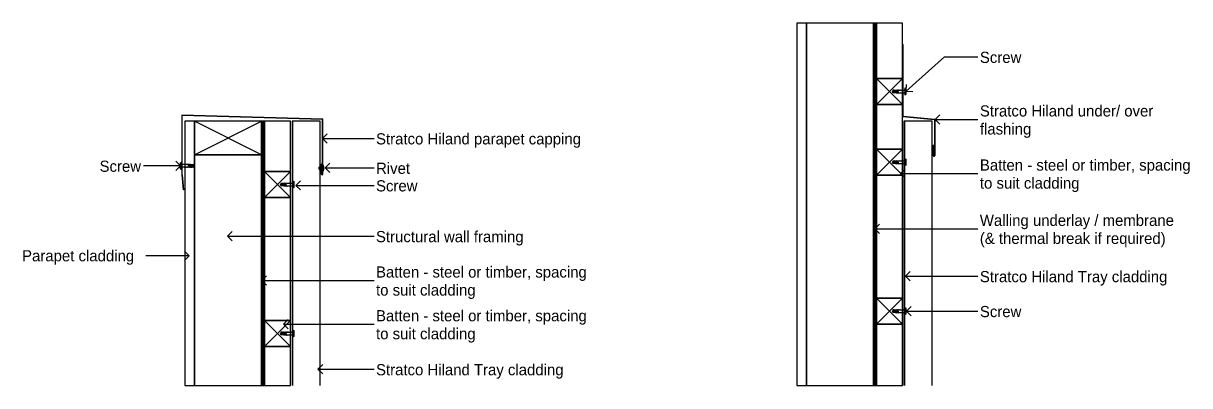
# Model space of a CAD drawing. Extents: x -2.36 to 6.66, y -3.72 to 4.13.
# Drawn here: x -2.359 to -0.792, y 3.645 to 4.131 of the extents above; entities that cross this region are included whole.
import ezdxf

# ---------------------------------------------------------------- set-up
doc = ezdxf.new("R2010")
doc.units = 0
for name, color, linetype in [('A-____-____-IDEN', 7, 'Continuous'), ('A-DETL-____-MEDM', 7, 'Continuous'), ('A-DETL-GENF-OTLN', 7, 'Continuous'), ('A-WALL-____-MCUT', 7, 'Continuous'), ('A-WALL-____-PATT', 7, 'Continuous'), ('A-WALL-FNSH-MCUT', 7, 'Continuous'), ('G-____-____-TEXT', 7, 'Continuous')]:
    doc.layers.add(name, color=color, linetype=linetype)

# ---------------------------------------------------------------- blocks, each defined once
blk = doc.blocks.new('Detail_Stratco_Cladding Side Profile - 38mm-Hiland Nailstrip Parapet')
at = {"layer": 'A-DETL-____-MEDM'}
for p, q in [((-1.9981, 4), (-1.9981, 3.645)), ((-1.9971, 4), (-1.9981, 4)), ((-1.9971, 3.645), (-1.9971, 4))]:
    blk.add_line(p, q, dxfattribs=at)
at = {"layer": 'A-DETL-GENF-OTLN'}
for p, q in [((-1.9601, 4), (-1.9981, 4)), ((-1.9601, 3.645), (-1.9601, 4))]:
    blk.add_line(p, q, dxfattribs=at)
blk = doc.blocks.new('Detail_Stratco_Hiland_Tray_Parapet - Rib Height 38mm-Hiland Nailstrip Parapet')
at = {"layer": 'A-DETL-GENF-OTLN'}
for p, q in [((-1.9566, 4.003), (-2.146, 4.008)), ((-2.146, 4.008), (-2.146, 3.928)), ((-2.1455, 3.928), (-2.1455, 4.0075)), ((-1.9571, 4.0025), (-2.1455, 4.0075)), ((-1.9571, 3.929), (-1.9571, 4.0025)), ((-1.9566, 3.929), (-1.9566, 4.003)), ((-1.9586, 3.929), (-1.9586, 3.943)), ((-1.9586, 3.943), (-1.9581, 3.943)), ((-1.9581, 3.929), (-1.9581, 3.943)), ((-2.146, 3.928), (-2.1445, 3.908)), ((-2.1455, 3.928), (-2.144, 3.908)), ((-2.144, 3.908), (-2.1445, 3.908))]:
    blk.add_line(p, q, dxfattribs=at)
for radius in [0.001, 0.0005]:
    blk.add_arc((-1.9576, 3.929), radius, 180, 0, dxfattribs=at)
blk = doc.blocks.new('DET_ST_Framing Detail Timber - 35x35 Batten-Hiland Nailstrip Parapet')
at = {"layer": 'A-DETL-____-MEDM'}
for p, q in [((-2, 3.9325), (-2.035, 3.9325)), ((-2.035, 3.9325), (-2.035, 3.8975)), ((-2, 3.8975), (-2, 3.9325)), ((-2.035, 3.8975), (-2, 3.8975))]:
    blk.add_line(p, q, dxfattribs=at)
at = {"layer": 'A-DETL-GENF-OTLN'}
for p, q in [((-2.035, 3.9325), (-2, 3.8975)), ((-2, 3.9325), (-2.035, 3.8975))]:
    blk.add_line(p, q, dxfattribs=at)
blk = doc.blocks.new('DET_ST_Framing Detail Timber - 45x90-Hiland Nailstrip Parapet')
at = {"layer": 'A-DETL-____-MEDM'}
for p, q in [((-2.039, 4), (-2.129, 4)), ((-2.129, 4), (-2.129, 3.955)), ((-2.039, 3.955), (-2.039, 4)), ((-2.129, 3.955), (-2.039, 3.955))]:
    blk.add_line(p, q, dxfattribs=at)
at = {"layer": 'A-DETL-GENF-OTLN'}
for p, q in [((-2.039, 3.955), (-2.129, 4)), ((-2.129, 3.955), (-2.039, 4))]:
    blk.add_line(p, q, dxfattribs=at)
blk = doc.blocks.new('DET_Screw Metal Wafer - DET_Screw Metal Wafer-Hiland Nailstrip Parapet')
at = {"layer": 'A-DETL-GENF-OTLN'}
for p, q in [((-1.9971, 3.9191), (-1.9971, 3.9109)), ((-1.9964, 3.9196), (-1.9955, 3.919)), ((-1.9964, 3.9104), (-1.9964, 3.9196)), ((-1.9955, 3.919), (-1.9955, 3.911)), ((-2.013, 3.9167), (-2.0136, 3.915)), ((-2.0136, 3.915), (-2.006, 3.915)), ((-2.0128, 3.9127), (-2.0136, 3.915)), ((-2.013, 3.9167), (-1.9979, 3.9167)), ((-2.0087, 3.9132), (-2.0128, 3.9127)), ((-2.0123, 3.9167), (-2.0121, 3.9175)), ((-2.0102, 3.9167), (-2.01, 3.9175)), ((-2.0087, 3.9132), (-1.9979, 3.9132)), ((-2.0084, 3.9125), (-2.0081, 3.9132)), ((-2.0081, 3.9167), (-2.0079, 3.9175)), ((-2.0063, 3.9125), (-2.006, 3.9132)), ((-2.006, 3.9167), (-2.0058, 3.9175)), ((-2.006, 3.915), (-2.0055, 3.9132)), ((-2.0042, 3.9125), (-2.0039, 3.9132)), ((-2.0039, 3.9167), (-2.0037, 3.9175)), ((-2.0021, 3.9125), (-2.0018, 3.9132)), ((-2.0018, 3.9167), (-2.0016, 3.9175)), ((-2, 3.9125), (-1.9997, 3.9132)), ((-1.9997, 3.9167), (-1.9995, 3.9175)), ((-1.9955, 3.911), (-1.9964, 3.9104))]:
    blk.add_line(p, q, dxfattribs=at)
for centre, radius, start, end in [((-1.9966, 3.9191), 0.0005, 66.3302, 180), ((-1.9979, 3.9175), 0.0008, 270, 0), ((-1.9979, 3.9124), 0.0008, 0, 90), ((-1.9966, 3.9109), 0.0005, 180, 293.6698)]:
    blk.add_arc(centre, radius, start, end, dxfattribs=at)
blk = doc.blocks.new('DET_Rivet - DET_Rivet-Hiland Nailstrip Parapet')
at = {"layer": 'A-DETL-GENF-OTLN'}
for p, q in [((-1.9621, 3.9377), (-1.9621, 3.9362)), ((-1.9601, 3.9377), (-1.9574, 3.9377)), ((-1.9601, 3.9362), (-1.9601, 3.9377)), ((-1.9601, 3.9362), (-1.9574, 3.9362)), ((-1.9566, 3.94), (-1.9566, 3.9385)), ((-1.9566, 3.9354), (-1.9566, 3.9385)), ((-1.9566, 3.9354), (-1.9566, 3.9338))]:
    blk.add_line(p, q, dxfattribs=at)
for centre, radius, start, end in [((-1.9611, 3.9377), 0.001, 0, 180), ((-1.9611, 3.9362), 0.001, 180, 0), ((-1.9574, 3.9385), 0.0008, 270, 0), ((-1.9574, 3.9354), 0.0008, 0, 90), ((-1.9561, 3.94), 0.0005, 52.978, 180), ((-1.9561, 3.9338), 0.0005, 180, 307.022), ((-1.9645, 3.9369), 0.00934, 337.9949, 22.0051)]:
    blk.add_arc(centre, radius, start, end, dxfattribs=at)
blk = doc.blocks.new('DET_ST_Framing Detail Timber - 35x35 Batten-Hiland Nailstrip Parapet 1')
at = {"layer": 'A-DETL-____-MEDM'}
for p, q in [((-2, 3.9625), (-2.035, 3.9625)), ((-2.035, 3.9625), (-2.035, 3.9275)), ((-2, 3.9275), (-2, 3.9625)), ((-2.035, 3.9275), (-2, 3.9275))]:
    blk.add_line(p, q, dxfattribs=at)
at = {"layer": 'A-DETL-GENF-OTLN'}
for p, q in [((-2.035, 3.9625), (-2, 3.9275)), ((-2, 3.9625), (-2.035, 3.9275))]:
    blk.add_line(p, q, dxfattribs=at)
blk = doc.blocks.new('Detail_Stratco_Cladding Side Profile - 38mm-Hiland Nailstrip Parapet 1')
at = {"layer": 'A-DETL-____-MEDM'}
for p, q in [((-1.9981, 4), (-1.9981, 3.645)), ((-1.9971, 4), (-1.9981, 4)), ((-1.9971, 3.645), (-1.9971, 4))]:
    blk.add_line(p, q, dxfattribs=at)
at = {"layer": 'A-DETL-GENF-OTLN'}
for p, q in [((-1.9601, 4), (-1.9981, 4)), ((-1.9601, 3.645), (-1.9601, 4))]:
    blk.add_line(p, q, dxfattribs=at)
blk = doc.blocks.new('Detail_Stratco_Hiland_Tray_Under Over Flashing - Rib Height 38mm-Hiland Nailstrip Parapet 1')
at = {"layer": 'A-DETL-GENF-OTLN'}
for p, q in [((-1.9997, 4.0063), (-1.9997, 4.103)), ((-1.9997, 4.103), (-1.9992, 4.103)), ((-1.9992, 4.0067), (-1.9992, 4.103)), ((-1.9997, 4.0063), (-1.9572, 4.0025)), ((-1.9992, 4.0067), (-1.9567, 4.003)), ((-1.9572, 4.0025), (-1.9572, 3.954)), ((-1.9567, 4.003), (-1.9567, 3.954)), ((-1.9587, 3.968), (-1.9587, 3.954)), ((-1.9587, 3.968), (-1.9582, 3.968)), ((-1.9582, 3.968), (-1.9582, 3.954))]:
    blk.add_line(p, q, dxfattribs=at)
for radius in [0.001, 0.0005]:
    blk.add_arc((-1.9577, 3.954), radius, 180, 0, dxfattribs=at)
blk = doc.blocks.new('DET_Screw Metal Wafer - DET_Screw Metal Wafer-Hiland Nailstrip Parapet 1')
at = {"layer": 'A-DETL-GENF-OTLN'}
for p, q in [((-1.9964, 3.9496), (-1.9955, 3.949)), ((-1.9964, 3.9404), (-1.9964, 3.9496)), ((-2.013, 3.9467), (-2.0136, 3.945)), ((-2.0136, 3.945), (-2.006, 3.945)), ((-2.0128, 3.9427), (-2.0136, 3.945)), ((-2.013, 3.9467), (-1.9979, 3.9467)), ((-2.0087, 3.9432), (-2.0128, 3.9427)), ((-2.0123, 3.9467), (-2.0121, 3.9475)), ((-2.0102, 3.9467), (-2.01, 3.9475)), ((-2.0087, 3.9432), (-1.9979, 3.9432)), ((-2.0084, 3.9425), (-2.0081, 3.9432)), ((-2.0081, 3.9467), (-2.0079, 3.9475)), ((-2.0063, 3.9425), (-2.006, 3.9432)), ((-2.006, 3.9467), (-2.0058, 3.9475)), ((-2.006, 3.945), (-2.0055, 3.9432)), ((-2.0042, 3.9425), (-2.0039, 3.9432)), ((-2.0039, 3.9467), (-2.0037, 3.9475)), ((-2.0021, 3.9425), (-2.0018, 3.9432)), ((-2.0018, 3.9467), (-2.0016, 3.9475)), ((-2, 3.9425), (-1.9997, 3.9432)), ((-1.9997, 3.9467), (-1.9995, 3.9475)), ((-1.9971, 3.9491), (-1.9971, 3.9409)), ((-1.9955, 3.941), (-1.9964, 3.9404)), ((-1.9955, 3.949), (-1.9955, 3.941))]:
    blk.add_line(p, q, dxfattribs=at)
for centre, radius, start, end in [((-1.9966, 3.9491), 0.0005, 66.3302, 180), ((-1.9979, 3.9475), 0.0008, 270, 0), ((-1.9979, 3.9425), 0.0008, 0, 90), ((-1.9966, 3.9409), 0.0005, 180, 293.6698)]:
    blk.add_arc(centre, radius, start, end, dxfattribs=at)

msp = doc.modelspace()

# ---------------------------------------------------------------- linework, layer by layer
at = {"layer": 'A-____-____-IDEN'}
for p, q in [((-1.1729, 4.0404), (-1.1212, 4.0864)), ((-1.1212, 4.0864), (-1.0765, 4.0864)), ((-1.1729, 4.0404), (-1.1724, 4.0492)), ((-1.1729, 4.0404), (-1.164, 4.0399)), ((-1.1341, 4.0024), (-1.1278, 4.0086)), ((-1.1341, 4.0024), (-1.1278, 3.9961)), ((-1.1341, 4.0024), (-1.1261, 4.0024)), ((-1.1261, 4.0024), (-1.0765, 4.0024)), ((-1.957, 3.977), (-1.9508, 3.9832)), ((-1.957, 3.977), (-1.9508, 3.9707)), ((-1.957, 3.977), (-1.9325, 3.977)), ((-1.9325, 3.977), (-1.8879, 3.977)), ((-2.1646, 3.9402), (-2.1978, 3.9402)), ((-2.1479, 3.9402), (-2.1646, 3.9402)), ((-2.1479, 3.9402), (-2.1542, 3.9465)), ((-2.1479, 3.9402), (-2.1542, 3.934)), ((-1.9535, 3.9375), (-1.9473, 3.9437)), ((-1.9535, 3.9375), (-1.9473, 3.9312)), ((-1.9535, 3.9375), (-1.943, 3.9375)), ((-1.943, 3.9375), (-1.8879, 3.9375)), ((-1.1806, 3.9297), (-1.1744, 3.936)), ((-1.9929, 3.9139), (-1.9867, 3.9202)), ((-1.1806, 3.9297), (-1.1744, 3.9235)), ((-1.1806, 3.9297), (-1.1621, 3.9297)), ((-1.1621, 3.9297), (-1.0765, 3.9297)), ((-1.9929, 3.9139), (-1.9867, 3.9077)), ((-1.9929, 3.9139), (-1.9518, 3.9139)), ((-1.9518, 3.9139), (-1.8879, 3.9139)), ((-1.2151, 3.8555), (-1.2088, 3.8617)), ((-1.2151, 3.8555), (-1.2088, 3.8492)), ((-1.2151, 3.8555), (-1.203, 3.8555)), ((-1.203, 3.8555), (-1.0765, 3.8555)), ((-2.0849, 3.8457), (-2.0786, 3.8519)), ((-2.0849, 3.8457), (-2.0786, 3.8394)), ((-2.0849, 3.8457), (-2.0481, 3.8457)), ((-2.0481, 3.8457), (-1.8879, 3.8457)), ((-1.1736, 3.792), (-1.1674, 3.7982)), ((-2.0385, 3.7861), (-2.0322, 3.7924)), ((-2.0385, 3.7861), (-2.0322, 3.7799)), ((-2.0385, 3.7861), (-2.0192, 3.7861)), ((-2.0192, 3.7861), (-1.8879, 3.7861)), ((-1.1736, 3.792), (-1.1674, 3.7857)), ((-1.1736, 3.792), (-1.1621, 3.792)), ((-1.1621, 3.792), (-1.0765, 3.792)), ((-1.1725, 3.7451), (-1.1662, 3.7514)), ((-2.0096, 3.7274), (-2.0033, 3.7337)), ((-1.1725, 3.7451), (-1.1662, 3.7389)), ((-1.1725, 3.7451), (-1.1454, 3.7451)), ((-1.1454, 3.7451), (-1.0765, 3.7451)), ((-2.0096, 3.7274), (-2.0033, 3.7212)), ((-2.0096, 3.7274), (-1.9842, 3.7274)), ((-1.9842, 3.7274), (-1.8879, 3.7274)), ((-1.9632, 3.667), (-1.9569, 3.6733)), ((-1.9632, 3.667), (-1.9569, 3.6608)), ((-1.9632, 3.667), (-1.943, 3.667)), ((-1.943, 3.667), (-1.8879, 3.667))]:
    msp.add_line(p, q, dxfattribs=at)
at = {"layer": 'A-WALL-____-MCUT'}
for p, q in [((-1.3067, 4.1315), (-1.3067, 3.645)), ((-1.2167, 4.1315), (-1.2167, 3.645)), ((-1.2147, 4.1315), (-1.2147, 3.645)), ((-1.2127, 4.1315), (-1.2127, 4.0575)), ((-1.1777, 4.0575), (-1.1777, 4.1315)), ((-1.2127, 4.0225), (-1.2127, 3.9625)), ((-1.1777, 3.9625), (-1.1777, 4.0225)), ((-2, 4), (-2.039, 4)), ((-2.037, 4), (-2.037, 3.645)), ((-2.035, 4), (-2.035, 3.9325)), ((-2, 3.9325), (-2, 4)), ((-2.129, 3.955), (-2.129, 3.645)), ((-2.039, 3.955), (-2.039, 3.645)), ((-1.2127, 3.9275), (-1.2127, 3.7625)), ((-1.1777, 3.7625), (-1.1777, 3.9275)), ((-2.035, 3.8975), (-2.035, 3.7325)), ((-2, 3.7325), (-2, 3.8975)), ((-1.2127, 3.7275), (-1.2127, 3.645)), ((-1.1777, 3.645), (-1.1777, 3.7275)), ((-2.035, 3.6975), (-2.035, 3.645)), ((-2, 3.645), (-2, 3.6975))]:
    msp.add_line(p, q, dxfattribs=at)
at = {"layer": 'A-WALL-____-PATT'}
for p, q in [((-1.3067, 4.1315), (-1.3197, 4.1315)), ((-1.3197, 4.1315), (-1.3197, 3.645)), ((-1.3067, 3.645), (-1.3067, 4.1315)), ((-1.2167, 4.1315), (-1.3067, 4.1315)), ((-1.3067, 4.1315), (-1.3067, 3.645)), ((-1.2167, 3.645), (-1.2167, 4.1315)), ((-1.2147, 4.1315), (-1.2167, 4.1315)), ((-1.2167, 4.1315), (-1.2167, 3.645)), ((-1.2147, 3.645), (-1.2147, 4.1315)), ((-1.2127, 4.1315), (-1.2147, 4.1315)), ((-1.2147, 4.1315), (-1.2147, 3.645)), ((-1.2127, 3.645), (-1.2127, 4.1315)), ((-1.1777, 4.1315), (-1.2127, 4.1315)), ((-1.2127, 4.1315), (-1.2127, 4.0575)), ((-1.1777, 4.0575), (-1.1777, 4.1315)), ((-1.2127, 4.0575), (-1.1777, 4.0575)), ((-1.1777, 4.0225), (-1.2127, 4.0225)), ((-1.2127, 4.0225), (-1.2127, 3.9625)), ((-1.1777, 3.9625), (-1.1777, 4.0225)), ((-2.129, 4), (-2.142, 4)), ((-2.142, 4), (-2.142, 3.955)), ((-2.129, 3.645), (-2.129, 4)), ((-2.037, 4), (-2.039, 4)), ((-2.039, 4), (-2.039, 3.645)), ((-2.037, 3.645), (-2.037, 4)), ((-2.035, 4), (-2.037, 4)), ((-2.037, 4), (-2.037, 3.645)), ((-2.035, 3.645), (-2.035, 4)), ((-2, 4), (-2.035, 4)), ((-2.035, 4), (-2.035, 3.9325)), ((-2, 3.9325), (-2, 4)), ((-2.142, 3.955), (-2.142, 3.645)), ((-2.039, 3.955), (-2.129, 3.955)), ((-2.129, 3.955), (-2.129, 3.645)), ((-2.039, 3.645), (-2.039, 3.955)), ((-1.2127, 3.9625), (-1.1777, 3.9625)), ((-2.035, 3.9325), (-2, 3.9325)), ((-1.1777, 3.9275), (-1.2127, 3.9275)), ((-1.2127, 3.9275), (-1.2127, 3.7625)), ((-1.1777, 3.7625), (-1.1777, 3.9275)), ((-2, 3.8975), (-2.035, 3.8975)), ((-2.035, 3.8975), (-2.035, 3.7325)), ((-2, 3.7325), (-2, 3.8975)), ((-1.2127, 3.7625), (-1.1777, 3.7625)), ((-2.035, 3.7325), (-2, 3.7325)), ((-1.1777, 3.7275), (-1.2127, 3.7275)), ((-1.2127, 3.7275), (-1.2127, 3.645)), ((-1.1777, 3.645), (-1.1777, 3.7275)), ((-2, 3.6975), (-2.035, 3.6975)), ((-2.035, 3.6975), (-2.035, 3.645)), ((-2, 3.645), (-2, 3.6975)), ((-2.142, 3.645), (-2.129, 3.645)), ((-2.129, 3.645), (-2.039, 3.645)), ((-2.039, 3.645), (-2.037, 3.645)), ((-2.037, 3.645), (-2.035, 3.645)), ((-2.035, 3.645), (-2, 3.645)), ((-1.3197, 3.645), (-1.3067, 3.645)), ((-1.3067, 3.645), (-1.2167, 3.645)), ((-1.2167, 3.645), (-1.2147, 3.645)), ((-1.2147, 3.645), (-1.2127, 3.645)), ((-1.2127, 3.645), (-1.1777, 3.645))]:
    msp.add_line(p, q, dxfattribs=at)
at = {"layer": 'A-WALL-FNSH-MCUT'}
for p, q in [((-1.3197, 4.1315), (-1.3197, 3.645)), ((-2.142, 4), (-2.142, 3.645)), ((-2.129, 4), (-2.142, 4))]:
    msp.add_line(p, q, dxfattribs=at)
at = {"layer": 'G-____-____-TEXT'}
for q in [(-2.1427, 3.8256), (-2.1946, 3.8194), (-2.1427, 3.8131)]:
    msp.add_line((-2.1364, 3.8194), q, dxfattribs=at)

# ---------------------------------------------------------------- block references
at = {"layer": 'A-DETL-GENF-OTLN'}
for name, p in [('Detail_Stratco_Hiland_Tray_Under Over Flashing - Rib Height 38mm-Hiland Nailstrip Parapet 1', (0.8223, 0)), ('DET_ST_Framing Detail Timber - 35x35 Batten-Hiland Nailstrip Parapet 1', (0.8223, 0.095)), ('DET_Screw Metal Wafer - DET_Screw Metal Wafer-Hiland Nailstrip Parapet 1', (0.8223, 0.095)), ('Detail_Stratco_Hiland_Tray_Parapet - Rib Height 38mm-Hiland Nailstrip Parapet', (0, 0)), ('DET_ST_Framing Detail Timber - 45x90-Hiland Nailstrip Parapet', (0, 0)), ('Detail_Stratco_Cladding Side Profile - 38mm-Hiland Nailstrip Parapet', (0, 0)), ('Detail_Stratco_Cladding Side Profile - 38mm-Hiland Nailstrip Parapet 1', (0.8223, 0)), ('DET_ST_Framing Detail Timber - 35x35 Batten-Hiland Nailstrip Parapet 1', (0.8223, 0)), ('DET_Screw Metal Wafer - DET_Screw Metal Wafer-Hiland Nailstrip Parapet 1', (0.8223, 0)), ('DET_Rivet - DET_Rivet-Hiland Nailstrip Parapet', (0, 0)), ('DET_ST_Framing Detail Timber - 35x35 Batten-Hiland Nailstrip Parapet', (0, 0)), ('DET_Screw Metal Wafer - DET_Screw Metal Wafer-Hiland Nailstrip Parapet', (0, 0)), ('DET_ST_Framing Detail Timber - 35x35 Batten-Hiland Nailstrip Parapet 1', (0.8223, -0.2)), ('DET_Screw Metal Wafer - DET_Screw Metal Wafer-Hiland Nailstrip Parapet 1', (0.8223, -0.2)), ('DET_ST_Framing Detail Timber - 35x35 Batten-Hiland Nailstrip Parapet', (0, -0.2)), ('DET_Screw Metal Wafer - DET_Screw Metal Wafer-Hiland Nailstrip Parapet', (0, -0.2))]:
    msp.add_blockref(name, p, dxfattribs=at)
at = {"layer": 'A-DETL-GENF-OTLN', "rotation": 180}
msp.add_blockref('DET_Screw Metal Wafer - DET_Screw Metal Wafer-Hiland Nailstrip Parapet', (-4.1433, 7.855), dxfattribs=at)

# ---------------------------------------------------------------- texts
at = {"layer": 'A-____-____-IDEN'}
for s, p in [('Screw', (-1.0738, 4.0783)), ('Stratco Hiland under/ over', (-1.0738, 4.0064)), ('flashing', (-1.0738, 3.9822)), ('Stratco Hiland parapet capping', (-1.8852, 3.9689)), ('Batten - steel or timber, spacing', (-1.0738, 3.9337)), ('Screw', (-2.2567, 3.9321)), ('Rivet', (-1.8852, 3.9294)), ('Screw', (-1.8852, 3.9058)), ('to suit cladding', (-1.0738, 3.9095)), ('Walling underlay / membrane', (-1.0739, 3.8595)), ('Structural wall framing', (-1.8853, 3.8376)), ('(& thermal break if required)', (-1.0739, 3.8353)), ('Batten - steel or timber, spacing', (-1.8852, 3.7901)), ('Stratco Hiland Tray cladding', (-1.0738, 3.7839)), ('to suit cladding', (-1.8852, 3.7659)), ('Batten - steel or timber, spacing', (-1.8852, 3.7314)), ('Screw', (-1.0738, 3.737)), ('to suit cladding', (-1.8852, 3.7073)), ('Stratco Hiland Tray cladding', (-1.8852, 3.6589))]:
    msp.add_text(s, height=0.015, dxfattribs=at).set_placement(p)
at = {"layer": 'G-____-____-TEXT'}
msp.add_text('Parapet cladding', height=0.015, dxfattribs=at).set_placement((-2.3608, 3.8119))

doc.saveas('drawing.dxf')
